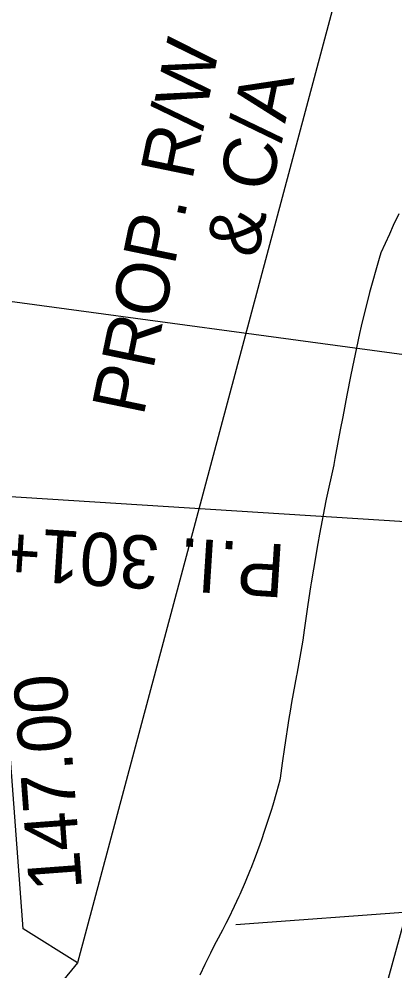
# Model space of a CAD drawing. Extents: x -70 to 701944, y -4 to 666871.
# Drawn here: x 664262.6 to 664305.1, y 656874.1 to 656981.7 of the extents above; entities that cross this region are included whole.
import ezdxf

# ---------------------------------------------------------------- set-up
doc = ezdxf.new("R2010")
doc.units = 0
for name, color, linetype in [('R_Detour', 7, 'Continuous'), ('R_Draft', 7, 'Continuous'), ('R_Horz Alg', 7, 'Continuous'), ('R_Horz Alg Annot', 7, 'Continuous'), ('R_No Plot', 7, 'Continuous'), ('R_Proposed Const Limits', 7, 'Continuous'), ('R_Proposed Road', 7, 'Continuous'), ('R_ROW', 7, 'Continuous'), ('R_Temp Easement Annot', 7, 'Continuous')]:
    doc.layers.add(name, color=color, linetype=linetype)

msp = doc.modelspace()

# ---------------------------------------------------------------- linework, layer by layer
at = {"layer": 'R_Detour'}
for p, q in [((664222.8, 656955.01), (664369.1, 656935.33)), ((664287.11, 656879.39), (664368.39, 656885.45))]:
    msp.add_line(p, q, dxfattribs=at)
at = {"layer": 'R_Draft'}
msp.add_arc((664209.62, 656892.35), 121, 317.3583, 2.4838, dxfattribs=at)
at = {"layer": 'R_Horz Alg'}
msp.add_arc((664209.62, 656892.35), 121, 317.3583, 2.4838, dxfattribs=at)
at = {"layer": 'R_Horz Alg Annot'}
msp.add_lwpolyline([(664365.74, 656921.11), (664222.35, 656930.19)], dxfattribs=at)
at = {"layer": 'R_No Plot'}
msp.add_lwpolyline([(664379.54, 656735.87), (664372.11, 656835.59), (664368.39, 656885.45), (664306.43, 656880.83), (664298.66, 656852.63), (664284.64, 656830.07)], close=True, dxfattribs=at)
at = {"layer": 'R_Proposed Const Limits'}
for points in [[(664292.16, 656895.93), (664292.4, 656897.63), (664292.66, 656899.42), (664293.16, 656902.68), (664293.29, 656903.48), (664293.45, 656904.46), (664294.01, 656907.52), (664294.05, 656907.69), (664294.72, 656911.53), (664294.87, 656912.64), (664295.3, 656915.53), (664295.61, 656917.55), (664295.68, 656917.99), (664295.93, 656919.52), (664296.43, 656922.42), (664296.62, 656923.49), (664297.33, 656927.24), (664297.37, 656927.44), (664298.24, 656931.33), (664298.24, 656931.36), (664298.36, 656932.02), (664298.97, 656935.29), (664299.25, 656936.76), (664299.71, 656939.2), (664300.17, 656941.48), (664300.5, 656943.1), (664300.8, 656944.52), (664301.14, 656946.15), (664301.33, 656946.99), (664302.26, 656950.77), (664302.28, 656950.84), (664303.36, 656954.67), (664303.57, 656955.32), (664304.52, 656957.42), (664304.97, 656958.38), (664305.58, 656959.7)], [(664283.07, 656873.72), (664283.67, 656874.9), (664284.29, 656876.19), (664284.47, 656876.62), (664284.95, 656877.49), (664285.64, 656878.79), (664286.04, 656879.56), (664286.32, 656880.12), (664286.97, 656881.46), (664287.5, 656882.61), (664287.6, 656882.83), (664288.2, 656884.21), (664288.78, 656885.61), (664288.84, 656885.75), (664289.34, 656887.03), (664289.87, 656888.47), (664290.05, 656888.99), (664290.37, 656889.93), (664290.85, 656891.4), (664291.15, 656892.31), (664291.33, 656892.9), (664291.77, 656894.4), (664292.12, 656895.72), (664292.17, 656895.92), (664292.17, 656895.93)]]:
    msp.add_lwpolyline(points, dxfattribs=at)
at = {"layer": 'R_Proposed Road'}
msp.add_arc((664209.62, 656892.35), 120, 317.3583, 2.4838, dxfattribs=at)
at = {"layer": 'R_ROW'}
msp.add_lwpolyline([(664304.96, 657008.59), (664269.22, 656875.05), (664229.69, 656826.98), (664172.91, 656800.84), (664112.65, 656789.66), (663906.51, 656801.43), (663861.11, 656796.12)], dxfattribs=at)
at = {"layer": 'R_Temp Easement Annot'}
msp.add_lwpolyline([(664269.22, 656875.05), (664263.07, 656878.9), (664260.47, 656913.8)], dxfattribs=at)

# ---------------------------------------------------------------- texts
at = {"layer": 'R_Horz Alg Annot'}
msp.add_text('P.I. 301+85.76', height=6, rotation=176.378, dxfattribs=at).set_placement((664292.84, 656922.31))
at = {"layer": 'R_ROW'}
for s, p in [('PROP. R/W ', (664276.67, 656936.7)), ('& C/A', (664289.54, 656954.54))]:
    msp.add_text(s, height=6, rotation=78.3395, dxfattribs=at).set_placement(p)
at = {"layer": 'R_Temp Easement Annot'}
msp.add_text('147.00', height=6, rotation=94.2619, dxfattribs=at).set_placement((664269.75, 656883.41))

doc.saveas('drawing.dxf')
